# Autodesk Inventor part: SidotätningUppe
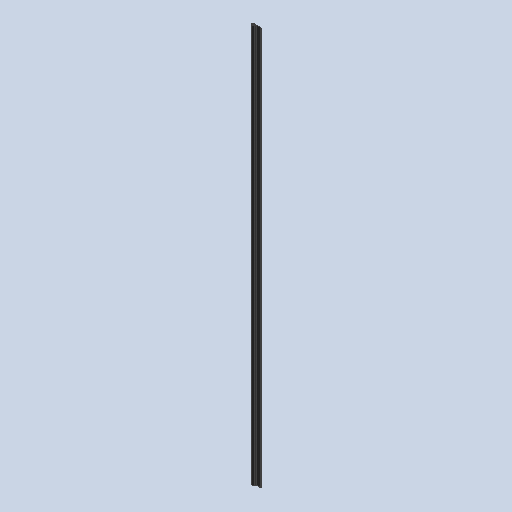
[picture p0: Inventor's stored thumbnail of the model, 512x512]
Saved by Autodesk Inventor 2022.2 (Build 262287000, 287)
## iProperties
Created: 2019-06
Part Number: SidotätningUppe
Material: Rubber
Document SubType Name: Modeling
Designer: cl
Density: 0.93 g/cm^3
Appearance: Rubber - Black
Author: cl
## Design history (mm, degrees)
sketch "Sketch1"
  geometry: L1 (0, 0)-(28, 0); L2 (33, -5)-(33, -15); L3 (28, -20)-(0, -20); L4 (0, -20)-(-50, -20); L5 (-50, -20)-(-50, -19); L6 (-50, -19)-(0, -19); L7 (0, 0)-(0, -19); A1 r 5 centre (28, -15) between (28, -20) and (33, -15); A2 r 5 centre (28, -5) between (33, -5) and (28, 0); 2 further points
  constraints: 14 end point, 4 point on circle, 4 point on line, 4 tangent, 2 centre point, 2 horizontal, 2 parallel, 2 perpendicular, 1 equal radius, 1 vertical
  dimensions: "d0" = 33 distance of point (33, -20) L3.end; "d1" = 20 distance of point (33, 0) point (33, -20); "d2" = 5 radius of A1; "d5" = 50 distance of L6.end L5.end; "d6" = 1 distance of L4.end L5.end; "d7" = 0 horizontal distance of L3.end L6.end
extrude "Extrusion1" new body sketch "Sketch1" distance "d3" = 4050 (computed from DagBredd); taper "d4" = 0 deg
body "Solid1"
other parameters: "BladBredd" = 987.5, "Fönsterhöjd" = 862
